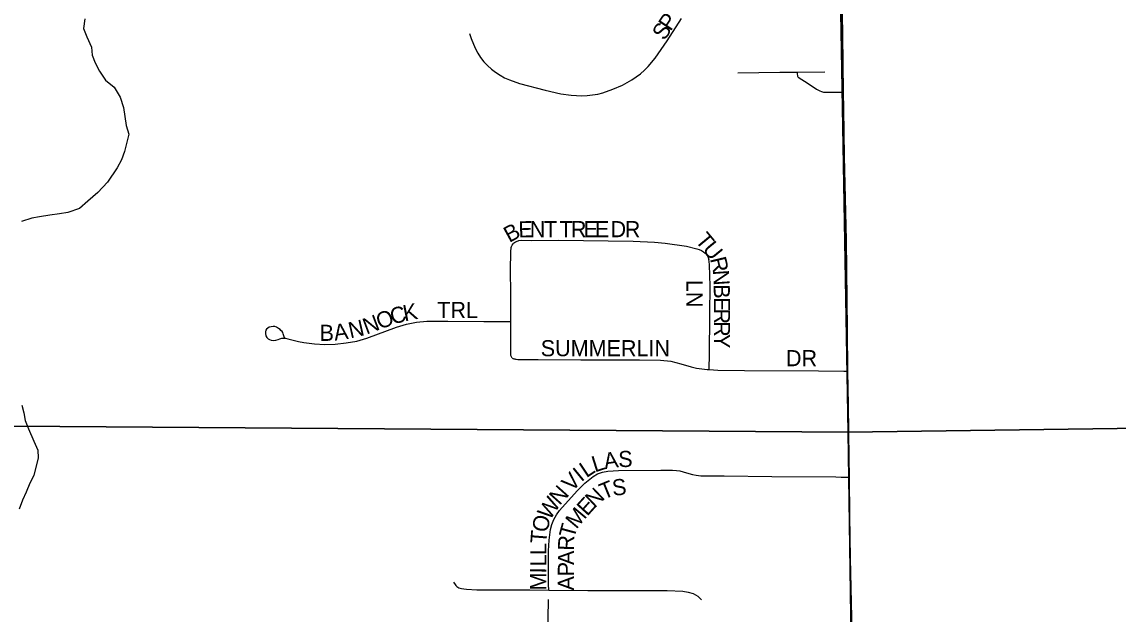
# Model space of a CAD drawing. Extents: x 1985906 to 2360102, y 891258 to 1222054.
# Drawn here: x 2127638 to 2131040, y 1035571 to 1037407 of the extents above; entities that cross this region are included whole.
import ezdxf

# ---------------------------------------------------------------- set-up
doc = ezdxf.new("R2010")
doc.units = 0
for name, color, linetype in [('GM_X_City_Street', 7, 'Continuous'), ('GM_X_City_Street_Text', 7, 'Continuous'), ('GM_X_Minor_River', 7, 'Continuous'), ('GM_X_Section', 7, 'Continuous')]:
    doc.layers.add(name, color=color, linetype=linetype)

msp = doc.modelspace()

# ---------------------------------------------------------------- linework, layer by layer
at = {"layer": 'GM_X_City_Street'}
for points in [[(2130188.5, 1037189.7), (2130186, 1037367.3), (2130183.6, 1037495.1), (2130183.1, 1037517.2)], [(2129027.5, 1037371.8), (2129032.3, 1037356), (2129045.3, 1037325.8), (2129052.8, 1037311.1), (2129061.5, 1037297.1), (2129071.5, 1037284.1), (2129082.9, 1037272.1), (2129095.2, 1037261.2), (2129108.3, 1037251.2), (2129122.1, 1037242.1), (2129136.5, 1037234.2), (2129151.5, 1037227.5), (2129182.7, 1037216.9), (2129262.5, 1037195.9), (2129310.7, 1037184.8), (2129343.2, 1037180), (2129376.2, 1037178.5), (2129392.6, 1037179.2), (2129409, 1037181), (2129425.2, 1037183.9), (2129441.2, 1037187.9), (2129472.4, 1037198.5), (2129502.6, 1037211.7), (2129531.4, 1037227.7), (2129545.1, 1037236.9), (2129558.1, 1037247), (2129570.5, 1037257.8), (2129582.1, 1037269.5), (2129603.2, 1037294.7), (2129640.6, 1037349), (2129685.3, 1037418.3)], [(2129859.7, 1037250), (2129991, 1037251.5), (2130044.8, 1037252.1)], [(2130044.8, 1037252.1), (2130044.8, 1037248.4), (2130044.7, 1037245), (2130044.9, 1037241.6), (2130045.6, 1037239.7), (2130046.5, 1037238), (2130047.9, 1037236.5), (2130078.5, 1037216.2), (2130104.6, 1037198.8), (2130114.6, 1037193.6), (2130120.1, 1037191.3), (2130125.9, 1037190.1), (2130133.7, 1037189.5), (2130146.8, 1037189.4), (2130160.3, 1037189.3), (2130176.9, 1037189.5), (2130188.5, 1037189.7)], [(2130044.8, 1037252.1), (2130130.1, 1037253.1)], [(2130202.1, 1036324.3), (2130200.8, 1036452.8), (2130197.5, 1036730.9), (2130193.4, 1036904.3), (2130191.7, 1036989.8), (2130189.3, 1037137.2), (2130188.5, 1037189.7)], [(2129155.5, 1036478), (2129156.1, 1036559.8), (2129155.1, 1036642.9), (2129155.8, 1036689.6), (2129155.8, 1036698), (2129156.3, 1036704.1), (2129156.6, 1036707.6), (2129157.4, 1036710.9)], [(2129157.4, 1036710.9), (2129159.5, 1036715.2), (2129162.8, 1036719.5), (2129164.4, 1036721.4), (2129166.9, 1036723.6), (2129169.9, 1036725.3), (2129173, 1036726.3), (2129180.1, 1036729), (2129190, 1036730), (2129220.3, 1036729.4), (2129303.2, 1036730.2), (2129535.3, 1036727.6), (2129601.4, 1036724.3), (2129634.7, 1036721.4), (2129700.7, 1036711.4), (2129732.5, 1036703.7), (2129740.1, 1036701.1), (2129747.2, 1036698.3), (2129753.6, 1036694.4), (2129759, 1036690.1), (2129762, 1036687), (2129765, 1036683.2), (2129766.6, 1036680), (2129768, 1036676.9), (2129769.8, 1036670.7)], [(2129771.2, 1036329.2), (2129771.4, 1036337.6), (2129772, 1036369.3), (2129773.3, 1036503.5), (2129774.4, 1036587.4), (2129772.6, 1036654.4), (2129771.3, 1036664), (2129769.8, 1036670.7)], [(2128452.9, 1036427.7), (2128449.3, 1036440.2), (2128447.7, 1036443.8), (2128445.6, 1036446.9), (2128442.3, 1036450.7), (2128439.3, 1036453.5), (2128434.9, 1036456.9), (2128428.6, 1036460.4), (2128423.5, 1036462.3), (2128417.8, 1036462.7), (2128411.3, 1036461.9), (2128406.1, 1036460.3), (2128401.4, 1036457.9), (2128397.6, 1036454.1), (2128395.6, 1036451.2), (2128394.4, 1036446.3), (2128394.2, 1036440.5), (2128395.3, 1036433.9), (2128398.2, 1036428.7), (2128403, 1036423.9), (2128406.4, 1036422), (2128411.4, 1036420.1), (2128418.9, 1036419.2), (2128426.6, 1036420.2), (2128433.1, 1036422), (2128438.6, 1036424), (2128444.8, 1036426), (2128450.2, 1036426.6), (2128455.9, 1036426.1), (2128463.5, 1036424.6), (2128496.8, 1036416.2), (2128513.2, 1036412.9), (2128546.1, 1036408.6), (2128578.5, 1036406.9), (2128610.3, 1036407.9), (2128644.9, 1036411.5), (2128677.4, 1036417.3), (2128709.2, 1036426), (2128800.9, 1036460.1), (2128831.8, 1036469.4), (2128863.2, 1036476), (2128895, 1036479.6), (2128959.8, 1036479.4), (2129072.2, 1036478.5), (2129136.8, 1036477.9), (2129155.5, 1036478)], [(2129160.3, 1036364.8), (2129158.5, 1036366.6), (2129157.4, 1036368.7), (2129156.6, 1036370.6), (2129156.1, 1036372.7), (2129155.7, 1036374.6), (2129155.4, 1036376.9), (2129155.3, 1036380.8), (2129155.3, 1036398.5), (2129155.4, 1036460.2), (2129155.5, 1036478)], [(2129160.3, 1036364.8), (2129161.6, 1036363.9), (2129163.4, 1036363.1), (2129165.4, 1036362.4), (2129167.6, 1036361.9), (2129169.7, 1036361.3), (2129172, 1036360.9), (2129177, 1036360.8), (2129199.3, 1036360.8), (2129240.8, 1036360.5), (2129372.8, 1036359.1), (2129554.6, 1036359.2), (2129620.1, 1036358.3), (2129652.2, 1036354.7), (2129683.7, 1036347.2), (2129715.3, 1036337.5), (2129731.7, 1036333.6), (2129764.9, 1036329.7), (2129771.2, 1036329.2)], [(2129771.2, 1036329.2), (2129798.2, 1036327), (2129880.9, 1036326), (2130110.9, 1036324.8), (2130189, 1036324.4), (2130202.1, 1036324.3)], [(2130206.3, 1035995.2), (2130205.6, 1036053.7), (2130203.2, 1036218.8), (2130202.1, 1036324.3)], [(2129273.1, 1035644.8), (2129273, 1035662.8), (2129272.8, 1035767), (2129274.4, 1035800.1), (2129278.7, 1035832.8), (2129282.6, 1035848.8), (2129288.9, 1035864), (2129297.3, 1035878.2), (2129307.1, 1035891.4), (2129361.6, 1035953.1), (2129385, 1035976.4), (2129410.8, 1035997), (2129425, 1036005.1), (2129440.5, 1036010.6), (2129456.8, 1036013.5), (2129489.6, 1036016), (2129621.4, 1036016.5), (2129657.1, 1036016.9), (2129670.1, 1036016.1), (2129680, 1036014.7), (2129701, 1036008.4), (2129719.5, 1036003.2), (2129731.3, 1036001), (2129745.6, 1035999.9), (2129817.7, 1035998.9), (2129966.2, 1035997.5), (2130164.1, 1035996.1), (2130180.6, 1035995.7), (2130206.3, 1035995.2)], [(2130219.3, 1035151.4), (2130219.2, 1035154.1), (2130219.2, 1035236), (2130217.7, 1035367.1), (2130214.8, 1035514.4), (2130210, 1035743.9), (2130207.6, 1035874.9), (2130206.3, 1035995.2)], [(2128977.6, 1035669.3), (2128982.4, 1035662), (2128984.6, 1035659.3), (2128987.6, 1035656.4), (2128990.8, 1035654.3), (2128994.2, 1035652.4), (2128998, 1035650.8), (2129002.1, 1035649.8), (2129009.6, 1035648.4), (2129018.1, 1035647.4), (2129050.6, 1035645.8), (2129214.6, 1035645.3), (2129273.1, 1035644.8)], [(2129270, 1035155.4), (2129269.9, 1035169), (2129269.9, 1035201.7), (2129270.1, 1035264.9), (2129270.5, 1035413.7), (2129270.9, 1035496.9), (2129272.2, 1035616.2)], [(2129273.1, 1035644.8), (2129394.8, 1035643.8), (2129575.2, 1035643.9), (2129640.8, 1035643.7), (2129689.7, 1035641.1), (2129705.9, 1035638.7), (2129721.4, 1035634.1), (2129735.7, 1035626.1), (2129747.8, 1035615.2)]]:
    msp.add_lwpolyline(points, dxfattribs=at)
at = {"layer": 'GM_X_Minor_River'}
for points in [[(2127833.2, 1037416.9), (2127829.6, 1037386.8), (2127839.9, 1037360.9), (2127854.4, 1037329), (2127856.7, 1037304.9), (2127865.1, 1037281)], [(2127865.1, 1037281), (2127879.5, 1037255.1), (2127897.9, 1037227.3), (2127924.3, 1037205.5), (2127942.8, 1037173.7), (2127953.2, 1037141.7), (2127962, 1037085.7), (2127970.4, 1037059.7), (2127957, 1037005.4), (2127947.3, 1036979.2), (2127933.6, 1036954.9), (2127904, 1036910.4), (2127874.3, 1036877.9), (2127842.5, 1036851.4), (2127816.7, 1036829), (2127780.7, 1036816.5), (2127754.7, 1036812.2), (2127724.6, 1036807.7), (2127692.6, 1036803.3), (2127668.5, 1036799), (2127636.5, 1036788.5)], [(2127637.9, 1036218.9), (2127644.2, 1036194.9), (2127648.5, 1036170.9), (2127658.9, 1036145), (2127675.5, 1036107.1), (2127687.9, 1036079.2), (2127688.2, 1036055.1), (2127674.8, 1036000.8), (2127663.1, 1035976.5), (2127651.4, 1035948.3), (2127639.7, 1035924.1), (2127630, 1035895.9)]]:
    msp.add_lwpolyline(points, dxfattribs=at)
at = {"layer": 'GM_X_Section'}
for points in [[(2130109.5, 1041463.5), (2135234.2, 1041549.5), (2135365.6, 1036205), (2130202.8, 1036134.8)], [(2124934, 1041489.3), (2130109.5, 1041463.5), (2130202.8, 1036134.8), (2125019.2, 1036172.5)], [(2130202.8, 1036134.8), (2135365.6, 1036205), (2135418, 1033901.9), (2135499.1, 1030852.6), (2130280.1, 1030804)], [(2125019.2, 1036172.5), (2130202.8, 1036134.8), (2130280.1, 1030804), (2125066.6, 1030831.6)]]:
    msp.add_lwpolyline(points, close=True, dxfattribs=at)

# ---------------------------------------------------------------- texts
at = {"layer": 'GM_X_City_Street_Text'}
for s, rotation, p in [('P', 56.416, (2129651.6, 1037376.5)), ('S', 56.4539, (2129632.2, 1037347.1)), ('B', 28.8682, (2129151, 1036721.5)), ('E', 1.0655, (2129179.5, 1036739)), ('N', 0.0656, (2129214.5, 1036739.7)), ('T', 0, (2129258.5, 1036739.7)), ('T', 0, (2129306.9, 1036739.7)), ('R', 0, (2129342.1, 1036739.7)), ('E', 0, (2129381.7, 1036739.7)), ('E', 0, (2129416.9, 1036739.7)), ('D', 0, (2129465.2, 1036739.7)), ('R', 0, (2129509.2, 1036739.7)), ('T', 309.5258, (2129725.7, 1036728.6)), ('U', 309.5201, (2129748.2, 1036701.5)), ('R', 283.2294, (2129773.5, 1036672.9)), ('LN', 270, (2129700.8, 1036607.3)), ('N', 273.9595, (2129782.2, 1036636.5)), ('B', 270.9472, (2129785.2, 1036593.3)), ('K', 10.9285, (2128825.9, 1036478.4)), ('TRL', 0, (2128927.3, 1036489.1)), ('E', 270.0547, (2129785.9, 1036553.9)), ('N', 20.58, (2128707.6, 1036437.3)), ('O', 20.58, (2128748.8, 1036452.7)), ('C', 15.8387, (2128788.9, 1036467.9)), ('R', 270, (2129785.9, 1036518.7)), ('B', 359.7814, (2128562.1, 1036418.2)), ('A', 7.8043, (2128609.3, 1036418.6)), ('N', 12.7562, (2128657.5, 1036425.4)), ('R', 269.9927, (2129785.9, 1036479.1)), ('Y', 269.9915, (2129785.9, 1036439.5)), ('SUMMERLIN', 0, (2129248.5, 1036370.3)), ('DR', 0, (2130009.7, 1036339.5)), ('L', 17.5365, (2129416.1, 1036009.8)), ('A', 8.5783, (2129447.6, 1036019.9)), ('S', 1.0655, (2129489.4, 1036026.3)), ('I', 39.2402, (2129374.1, 1035978.8)), ('L', 33.5233, (2129390.1, 1035991.9)), ('V', 47.1665, (2129345.5, 1035947.8)), ('S', 5.2538, (2129472.1, 1035937.5)), ('N', 48.185, (2129307.3, 1035905.5)), ('N', 43.4852, (2129415.5, 1035897.5)), ('T', 22.2479, (2129443.3, 1035925.1)), ('W', 56.128, (2129276.6, 1035859.4)), ('E', 47.9376, (2129392.6, 1035872.1)), ('M', 50.1338, (2129359.1, 1035832)), ('O', 76.4567, (2129268.1, 1035820.9)), ('T', 74.9964, (2129352.6, 1035803)), ('T', 85.6788, (2129265.8, 1035787.9)), ('L', 89.8574, (2129265.8, 1035753.7)), ('R', 88.0569, (2129351.7, 1035766.4)), ('L', 89.8574, (2129265.7, 1035718.5)), ('A', 89.7595, (2129351.5, 1035722.8)), ('P', 89.9727, (2129351.5, 1035687.7)), ('M', 89.8543, (2129265.5, 1035643.6)), ('I', 89.8252, (2129265.6, 1035696.4)), ('A', 90, (2129351.5, 1035643.7))]:
    msp.add_text(s, height=50, rotation=rotation, dxfattribs=at).set_placement(p)

doc.saveas('drawing.dxf')
